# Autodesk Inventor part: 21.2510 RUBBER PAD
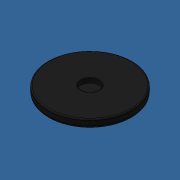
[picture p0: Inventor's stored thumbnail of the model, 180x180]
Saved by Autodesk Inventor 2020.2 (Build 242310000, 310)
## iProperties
Created: 2015-09
Part Number: 21.2510 RUBBER PAD
Material: NBR
Document SubType Name: Modeling
Mass: 29.1602 g
Surface Area: 95.2977 cm^2
Volume: 27.5097 cm^3
Density: 1.06 g/cm^3
Appearance: Schwarz
Description: 21.2510 RUBBER PAD
Beschreibung: zu Teller d 80 MT
Bezeichnung: Schwingungsdämpfer zu Teller d 80 MT
Artikelnr: 212908/1
Lieferantennr: 72401
Zeichnungsnr: 21-2908-1FZ.002
MiniTec_ID: 212908/1
Teileart: K
Lieferant: MiniTec
Author: MuellerJ
Title: Schwingungsdämpfer
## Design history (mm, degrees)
feature "Basis1"
feature "Körper verschieben1"
node "6C95"
other parameters: "d0" = 38.965, "d1" = -42.565, "d2" = -2.863
